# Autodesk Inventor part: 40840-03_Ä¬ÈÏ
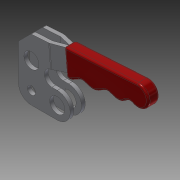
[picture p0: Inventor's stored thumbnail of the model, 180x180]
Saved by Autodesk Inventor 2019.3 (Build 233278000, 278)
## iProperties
Created: 2010-06
Part Number: 40840-03_Ä¬ÈÏ
Material: Ogólny
Document SubType Name: Modeling
Designer: CADENGINEERING4
Density: 1 g/cm^3
Appearance: Domyślna
Author: CADENGINEERING4
Revision Number: ÈÎºÎ
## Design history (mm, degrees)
feature "NONE"
node "Bryła1"
